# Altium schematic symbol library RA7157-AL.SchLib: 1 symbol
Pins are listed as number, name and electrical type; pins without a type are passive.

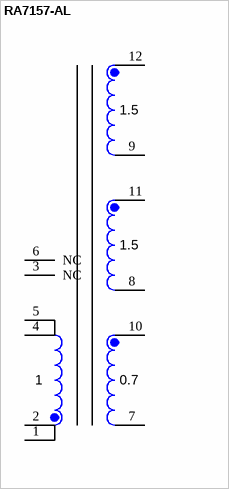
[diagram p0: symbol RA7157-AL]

## RA7157-AL
designator T?
1:1.5:1.5:0.7 Turns Ratio Transformer; Manufacturer: Coilcraft; SymbolCreator: a0412036; U/M: EA
footprint RA7157-AL (COILCRAFT RA7157-AL CUSTOM TRANSFORMER)
pins: 1, 2, 3 NC, 4, 5, 6 NC, 7, 8, 9, 10, 11, 12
